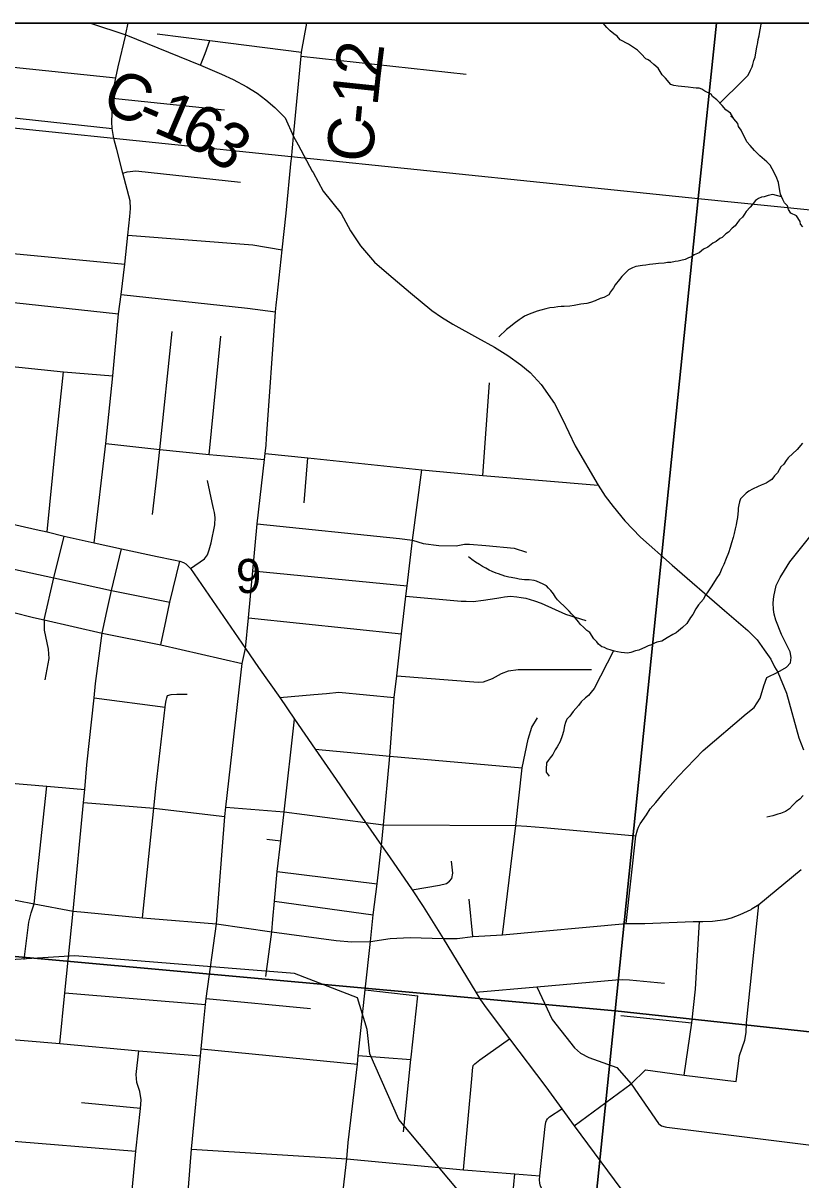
# Model space of a CAD drawing. Extents: x 0 to 34, y -2 to 22.
# Drawn here: x 5.715 to 6.671, y 19.479 to 20.9 of the extents above; entities that cross this region are included whole.
import ezdxf

# ---------------------------------------------------------------- set-up
doc = ezdxf.new("R2010")
doc.units = 0
for name, color, linetype in [('Default', 7, 'Continuous'), ('GM_X_City_Street', 7, 'Continuous'), ('GM_X_County_Road', 7, 'Continuous'), ('GM_X_County_Road_Text', 7, 'Continuous'), ('GM_X_Minor_River', 7, 'Continuous'), ('GM_X_Rail_Line', 7, 'Continuous'), ('GM_X_Section', 7, 'Continuous'), ('GM_X_Section_Text', 7, 'Continuous'), ('GM_X_Township_Road', 7, 'Continuous'), ('SH_Cut_Line', 7, 'Continuous'), ('SH_Data', 7, 'Continuous')]:
    doc.layers.add(name, color=color, linetype=linetype)

msp = doc.modelspace()

# ---------------------------------------------------------------- linework, layer by layer
at = {"layer": 'Default'}
for points in [[(6.5677, 20.9), (5.5559, 20.9), (5.5442, 20.7879), (6.545, 20.6847)], [(7.5861, 20.9), (6.5677, 20.9), (6.545, 20.6847), (7.556, 20.5828)]]:
    msp.add_lwpolyline(points, close=True, dxfattribs=at)
at = {"layer": 'GM_X_City_Street'}
for p, q in [((5.5426, 20.8625), (5.8293, 20.833)), ((5.8442, 20.6398), (5.9979, 20.6276)), ((5.9979, 20.6276), (6.0338, 20.6217)), ((5.6947, 20.618), (5.8404, 20.6041)), ((5.6889, 20.5585), (5.8326, 20.5432)), ((5.8357, 20.5667), (5.991, 20.5499)), ((5.991, 20.5499), (6.0255, 20.5455)), ((5.9441, 20.3701), (5.9584, 20.5157)), ((6.2803, 20.3443), (6.2886, 20.4581)), ((5.9722, 20.3677), (6.0119, 20.3641)), ((6.061, 20.3109), (6.0653, 20.366)), ((5.9978, 20.2273), (6.1873, 20.2088)), ((5.8242, 20.2031), (5.8955, 20.1888)), ((5.9922, 20.1698), (6.1806, 20.15)), ((5.8028, 20.0713), (5.8901, 20.0599)), ((6.0148, 19.898), (6.0321, 19.8958)), ((6.0277, 19.8583), (6.1504, 19.8429)), ((6.0242, 19.8218), (6.1458, 19.8051)), ((6.2681, 19.7782), (6.2636, 19.8243)), ((6.0136, 19.7293), (6.0209, 19.784)), ((5.7665, 19.7093), (5.9396, 19.6946)), ((6.1358, 19.713), (6.2003, 19.7054)), ((5.9404, 19.7023), (6.0684, 19.6897)), ((6.45, 19.6814), (6.5371, 19.6724)), ((5.9343, 19.6403), (6.1263, 19.6215)), ((6.1272, 19.632), (6.192, 19.6272)), ((5.8596, 19.5672), (5.787, 19.5739)), ((5.6223, 19.5336), (5.854, 19.5145)), ((6.3107, 19.3928), (6.3197, 19.4868))]:
    msp.add_line(p, q, dxfattribs=at)
for points in [[(5.5362, 20.8025), (5.5979, 20.7958), (5.6528, 20.7895), (5.7117, 20.783), (5.8247, 20.7706)], [(5.8381, 20.7158), (5.8433, 20.7173), (5.854, 20.7186), (5.9824, 20.7047)], [(5.8745, 20.2965), (5.8797, 20.3424), (5.8835, 20.3764), (5.8985, 20.5213)], [(5.3723, 20.5125), (5.4481, 20.5052), (5.4952, 20.5), (5.5069, 20.4989), (5.5672, 20.4926), (5.5757, 20.4918), (5.6223, 20.4867), (5.6349, 20.4853), (5.6824, 20.4803), (5.7652, 20.4718), (5.8255, 20.4667)], [(5.7448, 20.2751), (5.7552, 20.3787), (5.7652, 20.4718)], [(5.817, 20.3837), (5.8835, 20.3764), (5.9441, 20.3701), (5.9722, 20.3677)], [(6.1558, 19.89), (6.1584, 19.9154), (6.1659, 19.9998), (6.1716, 20.0719), (6.1746, 20.0984), (6.1806, 20.15), (6.1859, 20.1964), (6.1873, 20.2088), (6.1938, 20.2652), (6.2055, 20.3514)], [(5.921, 20.2302), (5.9383, 20.2423), (5.9421, 20.2472), (5.9441, 20.253), (5.9466, 20.2616), (5.9509, 20.2837), (5.9514, 20.2929), (5.9507, 20.2989), (5.9495, 20.304), (5.9478, 20.3112), (5.9419, 20.3382)], [(6.6431, 20.1028), (6.6535, 20.1089), (6.6584, 20.1145), (6.6594, 20.1209), (6.6581, 20.1278), (6.6475, 20.1493), (6.6405, 20.1667), (6.6386, 20.1742), (6.6375, 20.1801), (6.6374, 20.1882), (6.6382, 20.1957), (6.641, 20.2095), (6.6458, 20.2193), (6.6512, 20.2278), (6.6577, 20.2386), (6.7186, 20.3145)], [(6.0029, 20.2853), (6.1781, 20.2672), (6.1938, 20.2652), (6.2069, 20.261), (6.2264, 20.2584), (6.2475, 20.2582), (6.2578, 20.26), (6.2639, 20.2603), (6.2842, 20.2583), (6.3187, 20.2553), (6.3341, 20.2504)], [(5.5365, 20.2691), (5.644, 20.2442), (5.6871, 20.2331), (5.753, 20.2188), (5.8242, 20.2031)], [(5.7414, 20.1671), (5.753, 20.2188), (5.7659, 20.27)], [(5.8184, 20.1773), (5.8242, 20.2031), (5.8361, 20.2544)], [(5.8846, 20.1366), (5.8914, 20.1673), (5.8955, 20.1888), (5.9081, 20.2391)], [(5.5169, 20.2194), (5.6331, 20.1925), (5.6762, 20.183), (5.7281, 20.17)], [(6.1859, 20.1964), (6.2539, 20.1902), (6.2601, 20.1902), (6.2685, 20.1899), (6.281, 20.1912), (6.2974, 20.1939), (6.3025, 20.1946), (6.3072, 20.1956), (6.3145, 20.1962), (6.3221, 20.1954), (6.3276, 20.1947), (6.3331, 20.194), (6.3439, 20.1907), (6.3519, 20.1878), (6.3819, 20.1741), (6.407, 20.1665)], [(5.7604, 19.6469), (5.7665, 19.7093), (5.777, 19.8093), (5.7896, 19.9428), (5.7914, 19.9589), (5.7937, 19.9893), (5.8028, 20.0713), (5.8042, 20.0892), (5.8127, 20.151), (5.8184, 20.1773)], [(5.7281, 20.17), (5.7414, 20.1671), (5.8127, 20.151), (5.8846, 20.1366), (5.9848, 20.1137)], [(5.7414, 20.1671), (5.7414, 20.1544), (5.7463, 20.131), (5.7469, 20.1197), (5.7419, 20.0934)], [(6.1746, 20.0984), (6.2746, 20.0905), (6.2812, 20.091), (6.2922, 20.0953), (6.3035, 20.1011), (6.3118, 20.1045), (6.3237, 20.1061), (6.4138, 20.1064)], [(6.4739, 19.9168), (6.4814, 19.9277), (6.4862, 19.9349), (6.4928, 19.9429), (6.5042, 19.9564), (6.5204, 19.9749), (6.5511, 20.0067), (6.6042, 20.0518), (6.6137, 20.0595), (6.6214, 20.0711), (6.6257, 20.0861), (6.6295, 20.0964), (6.6431, 20.1028)], [(5.8901, 20.0599), (5.8904, 20.0636), (5.891, 20.0681), (5.8919, 20.0716), (5.893, 20.0741), (5.8974, 20.0757), (5.9043, 20.0758), (5.9168, 20.0758)], [(6.031, 20.0717), (6.0727, 20.0754), (6.0883, 20.0769), (6.1034, 20.0782), (6.1716, 20.0719)], [(5.8622, 19.8013), (5.8762, 19.9358), (5.8791, 19.9642), (5.8901, 20.0599)], [(6.0209, 19.784), (6.0221, 19.7995), (6.0242, 19.8218), (6.0277, 19.8583), (6.0321, 19.8958), (6.0363, 19.9314), (6.049, 20.0452)], [(6.3045, 19.7805), (6.3208, 19.9147), (6.3286, 19.9854), (6.3363, 20.0205), (6.3405, 20.0352), (6.3475, 20.0469)], [(6.0743, 20.0083), (6.1659, 19.9998), (6.3286, 19.9854)], [(5.696, 19.967), (5.7445, 19.963), (5.7914, 19.9589)], [(5.7166, 19.7502), (5.7223, 19.7959), (5.7252, 19.8073), (5.7288, 19.8186), (5.7445, 19.963)], [(5.7896, 19.9428), (5.8762, 19.9358), (5.9632, 19.9256)], [(5.9644, 19.9373), (6.0363, 19.9314), (6.1362, 19.9184), (6.1584, 19.9154), (6.3208, 19.9147), (6.3344, 19.9139), (6.3548, 19.9122), (6.4683, 19.9018)], [(6.4567, 19.7942), (6.4683, 19.9018), (6.4704, 19.9092), (6.4716, 19.9127), (6.4739, 19.9168)], [(6.1935, 19.8358), (6.2271, 19.8413), (6.2357, 19.8433), (6.2393, 19.8461), (6.2423, 19.8495), (6.2434, 19.8559), (6.2418, 19.8707)], [(6.5918, 19.6002), (6.596, 19.6322), (6.6022, 19.6511), (6.6039, 19.6605), (6.6045, 19.6724), (6.6194, 19.8178)], [(6.528, 19.6082), (6.5371, 19.6724), (6.5416, 19.7135), (6.5467, 19.7969)], [(6.2719, 19.7099), (6.3467, 19.7164), (6.4438, 19.7251), (6.4522, 19.7256), (6.4606, 19.7249), (6.5037, 19.721)], [(6.1828, 19.5386), (6.192, 19.6272), (6.1923, 19.63), (6.2003, 19.7054)], [(6.3467, 19.7164), (6.3655, 19.6762), (6.3932, 19.6417), (6.4006, 19.635), (6.4107, 19.6299), (6.445, 19.6176), (6.4627, 19.5973)], [(5.4355, 19.674), (5.5708, 19.6629), (5.6385, 19.657), (5.7604, 19.6469), (5.8575, 19.6381), (5.9334, 19.6318)], [(6.2566, 19.4917), (6.2673, 19.6079), (6.2678, 19.614), (6.2685, 19.6197), (6.2706, 19.6221), (6.2766, 19.6269), (6.3131, 19.6527)], [(5.8266, 19.2889), (5.8302, 19.2918), (5.8333, 19.2974), (5.834, 19.3028), (5.8363, 19.3336), (5.8443, 19.4023), (5.8486, 19.4579), (5.854, 19.5145), (5.8596, 19.5672), (5.8604, 19.5777), (5.8587, 19.5879), (5.8552, 19.599), (5.8544, 19.609), (5.8575, 19.6381)], [(6.3927, 19.5459), (6.4627, 19.5973), (6.4802, 19.6144), (6.5248, 19.6086), (6.528, 19.6082), (6.5918, 19.6002)], [(6.4627, 19.5973), (6.4962, 19.5486), (6.4984, 19.547), (6.5001, 19.546), (6.5046, 19.5445), (6.5064, 19.5442), (6.9768, 19.4858)], [(6.4415, 19.3501), (6.3546, 19.4656), (6.3512, 19.4716), (6.3503, 19.4752), (6.3501, 19.4793), (6.3504, 19.4845), (6.3571, 19.5449), (6.3579, 19.5501), (6.3585, 19.5524), (6.3597, 19.5544), (6.3625, 19.557), (6.3774, 19.5668)], [(5.9224, 19.5172), (6.1133, 19.5051), (6.2566, 19.4917), (6.3197, 19.4868), (6.3504, 19.4845)]]:
    msp.add_lwpolyline(points, dxfattribs=at)
at = {"layer": 'GM_X_County_Road'}
for p, q in [((5.7982, 20.9), (5.8415, 20.8855)), ((5.8265, 20.7609), (5.8247, 20.7706)), ((6.0451, 20.7329), (6.0478, 20.7608))]:
    msp.add_line(p, q, dxfattribs=at)
for points in [[(5.8415, 20.8855), (5.8417, 20.8867), (5.8444, 20.9)], [(6.0478, 20.7608), (6.0573, 20.8595), (6.0577, 20.8642), (6.0639, 20.9)], [(5.8293, 20.833), (5.832, 20.8462), (5.8415, 20.8855)], [(5.8415, 20.8855), (5.9071, 20.8592), (5.9333, 20.8482), (5.9592, 20.8374), (5.9734, 20.8306), (5.9903, 20.8218), (6.0029, 20.8138), (6.0136, 20.8058), (6.0246, 20.7962), (6.0376, 20.7839), (6.0478, 20.7608), (6.0533, 20.7507), (6.0708, 20.7184), (6.0718, 20.7166)], [(5.8803, 20.8868), (5.9449, 20.8786), (6.0577, 20.8642)], [(5.9333, 20.8482), (5.9392, 20.8629), (5.9449, 20.8786)], [(5.8252, 20.808), (5.8256, 20.8148), (5.8293, 20.833)], [(5.8247, 20.7706), (5.8246, 20.7787), (5.825, 20.7891), (5.8252, 20.808)], [(5.8029, 20.2617), (5.817, 20.3837), (5.8255, 20.4667), (5.8326, 20.5432), (5.8357, 20.5667), (5.8404, 20.6041), (5.8442, 20.6398), (5.8466, 20.6626), (5.8474, 20.6723), (5.8468, 20.6817), (5.8381, 20.7158), (5.8304, 20.7449), (5.8279, 20.755), (5.8265, 20.7609)], [(6.0275, 20.5642), (6.0338, 20.6217), (6.0387, 20.6667), (6.0449, 20.7311), (6.0451, 20.7329)], [(6.0718, 20.7166), (6.0842, 20.6937), (6.1061, 20.6664), (6.1176, 20.6448), (6.1302, 20.6264), (6.1473, 20.6066), (6.1649, 20.5911), (6.1914, 20.5686), (6.2178, 20.5469), (6.2295, 20.5388), (6.2435, 20.5304), (6.274, 20.5137), (6.2949, 20.5021), (6.3113, 20.492), (6.3272, 20.4802), (6.3385, 20.4709), (6.3519, 20.4561), (6.3686, 20.4329), (6.3784, 20.4137), (6.3939, 20.381), (6.422, 20.3325), (6.4306, 20.3191), (6.4407, 20.3065), (6.4549, 20.2886), (6.4742, 20.2686), (6.5129, 20.2344), (6.5774, 20.1785), (6.606, 20.1542), (6.6175, 20.1425), (6.626, 20.1304), (6.6343, 20.1187), (6.6389, 20.1095), (6.6431, 20.1028), (6.6535, 20.077), (6.6688, 20.0221), (6.6745, 20.0075)], [(6.0139, 20.3818), (6.0146, 20.3901), (6.0255, 20.5455), (6.0264, 20.5536), (6.0275, 20.5642)], [(5.9885, 20.1319), (5.9922, 20.1698), (5.9978, 20.2273), (6.0029, 20.2853), (6.0119, 20.3641), (6.013, 20.3714), (6.0139, 20.3818)], [(6.013, 20.3714), (6.0653, 20.366), (6.2055, 20.3514), (6.2803, 20.3443), (6.422, 20.3325)], [(5.6923, 20.2871), (5.7313, 20.2782), (5.7448, 20.2751), (5.7659, 20.27), (5.8029, 20.2617), (5.8361, 20.2544), (5.8802, 20.2451), (5.9002, 20.2408), (5.9081, 20.2391)], [(5.9081, 20.2391), (5.9123, 20.2377), (5.9154, 20.2361), (5.9179, 20.2335), (5.921, 20.2302)], [(5.921, 20.2302), (5.9885, 20.1319), (6.0047, 20.1087), (6.031, 20.0717), (6.049, 20.0452), (6.0743, 20.0083), (6.1, 19.9711), (6.1362, 19.9184), (6.1558, 19.89), (6.1657, 19.876), (6.1935, 19.8358), (6.2069, 19.815), (6.2317, 19.776), (6.2719, 19.7099), (6.2775, 19.7006), (6.2844, 19.6909), (6.3131, 19.6527), (6.3577, 19.5936), (6.3774, 19.5668), (6.3927, 19.5459), (6.4991, 19.4022)], [(5.9014, 19.2974), (5.9131, 19.3966), (5.9224, 19.5172), (5.9334, 19.6318), (5.9343, 19.6403), (5.9375, 19.6743), (5.9396, 19.6946), (5.9404, 19.7023), (5.9529, 19.7939), (5.9632, 19.9256), (5.9644, 19.9373), (5.9848, 20.1137), (5.9885, 20.1319)], [(6.08, 19.2123), (6.099, 19.3814), (6.1133, 19.5051), (6.115, 19.5254), (6.1263, 19.6215), (6.1272, 19.632), (6.1358, 19.713), (6.1423, 19.7722), (6.1458, 19.8051), (6.1504, 19.8429), (6.1558, 19.89)], [(6.6116, 19.8127), (6.6194, 19.8178), (6.6716, 19.8607)], [(5.4525, 19.8485), (5.6558, 19.829), (5.6871, 19.8259), (5.6955, 19.8249), (5.7082, 19.8225), (5.7288, 19.8186), (5.777, 19.8093), (5.791, 19.808), (5.8622, 19.8013), (5.8723, 19.8005)], [(6.2317, 19.776), (6.249, 19.776), (6.2681, 19.7782), (6.3045, 19.7805), (6.4567, 19.7942), (6.4793, 19.7942), (6.539, 19.7968), (6.5467, 19.7969), (6.5507, 19.7969), (6.5627, 19.7971), (6.5781, 19.7993), (6.5858, 19.8014), (6.5968, 19.8052), (6.6101, 19.8116), (6.6116, 19.8127)], [(5.8723, 19.8005), (5.9529, 19.7939), (6.0209, 19.784), (6.1002, 19.7735), (6.1192, 19.7716), (6.1423, 19.7722), (6.1665, 19.7758), (6.1911, 19.7772), (6.2317, 19.776)]]:
    msp.add_lwpolyline(points, dxfattribs=at)
at = {"layer": 'GM_X_Minor_River'}
for points in [[(6.6735, 20.6497), (6.671, 20.6532), (6.6703, 20.6563), (6.6659, 20.6632), (6.6588, 20.6665), (6.6559, 20.6711), (6.6549, 20.6757), (6.6511, 20.6793), (6.649, 20.6835), (6.6461, 20.6901), (6.6455, 20.6939), (6.6438, 20.7042), (6.641, 20.7115), (6.6359, 20.7212), (6.6334, 20.7255), (6.6293, 20.7298), (6.6208, 20.7369), (6.6141, 20.7435), (6.6089, 20.7498), (6.6049, 20.7544), (6.6031, 20.7579), (6.6002, 20.7633), (6.5977, 20.7684), (6.5947, 20.773), (6.5937, 20.7768), (6.5889, 20.7823), (6.5849, 20.7893), (6.5789, 20.7936), (6.5745, 20.7987), (6.5679, 20.8057), (6.5627, 20.8097), (6.5612, 20.8128), (6.5533, 20.8164), (6.5496, 20.8188), (6.5462, 20.8201), (6.5424, 20.8202), (6.539, 20.8206), (6.5329, 20.8212), (6.5204, 20.8227), (6.5151, 20.8236), (6.5113, 20.8248), (6.5047, 20.8323), (6.5006, 20.8366), (6.4959, 20.8447), (6.4907, 20.849), (6.4866, 20.853), (6.4836, 20.8549), (6.4806, 20.8562), (6.4751, 20.8624), (6.4703, 20.8667), (6.4594, 20.8743), (6.4493, 20.8795), (6.4456, 20.8838), (6.4415, 20.887), (6.4367, 20.8905), (6.4326, 20.8948), (6.4281, 20.9)], [(6.5718, 20.8016), (6.5997, 20.8292), (6.6024, 20.8322), (6.6063, 20.8359), (6.6092, 20.8423), (6.6116, 20.8464), (6.6124, 20.8494), (6.6133, 20.854), (6.6149, 20.8581), (6.6154, 20.8612), (6.6172, 20.8706), (6.6185, 20.8763), (6.6189, 20.8797), (6.6198, 20.8843), (6.6207, 20.8896), (6.6216, 20.8937), (6.6225, 20.8987), (6.6228, 20.9)], [(6.5882, 20.7835), (6.585, 20.7852)], [(6.6475, 20.6868), (6.6366, 20.6896), (6.6309, 20.6882), (6.6263, 20.6868), (6.6228, 20.6862), (6.619, 20.6847), (6.6155, 20.6822), (6.6112, 20.677), (6.6088, 20.674), (6.6041, 20.6688), (6.6021, 20.6654), (6.5997, 20.6617), (6.5958, 20.6583), (6.5934, 20.655), (6.5907, 20.6509), (6.5868, 20.6483), (6.5825, 20.6431), (6.579, 20.6413), (6.5747, 20.6369), (6.5716, 20.6354), (6.5673, 20.6317), (6.5631, 20.6299), (6.5569, 20.6248), (6.5515, 20.6226), (6.5464, 20.6178), (6.5403, 20.6153), (6.5368, 20.6128), (6.533, 20.6117), (6.5291, 20.6096), (6.5237, 20.6086), (6.5203, 20.6075), (6.5169, 20.6072), (6.5115, 20.6062), (6.5073, 20.606), (6.5031, 20.6053), (6.4963, 20.6048), (6.4932, 20.6045), (6.4894, 20.6038), (6.4852, 20.6036), (6.4806, 20.6029), (6.4768, 20.6023), (6.4684, 20.601), (6.4642, 20.5996), (6.4595, 20.597), (6.456, 20.5937), (6.4513, 20.5889), (6.4482, 20.5852), (6.4431, 20.5785), (6.4411, 20.5751), (6.4371, 20.5699), (6.4351, 20.5665), (6.429, 20.5632), (6.4247, 20.5618), (6.4186, 20.559), (6.4128, 20.5568), (6.4082, 20.5558), (6.401, 20.5549), (6.3926, 20.5532), (6.3872, 20.5526), (6.3804, 20.552), (6.3766, 20.5518), (6.3724, 20.5515), (6.3682, 20.5508), (6.3628, 20.5502), (6.3579, 20.5492), (6.3517, 20.5475), (6.3471, 20.5461), (6.3375, 20.5426), (6.3317, 20.5401), (6.3287, 20.5382), (6.3252, 20.5357), (6.319, 20.5313), (6.3143, 20.5276), (6.3096, 20.5239), (6.2999, 20.5147)], [(6.6732, 20.3843), (6.6665, 20.3765), (6.6556, 20.3661), (6.6532, 20.3627), (6.6504, 20.3582), (6.6465, 20.3549), (6.6426, 20.3478), (6.639, 20.3441), (6.6355, 20.3396), (6.6324, 20.3374), (6.6285, 20.3349), (6.6224, 20.3327), (6.6189, 20.3309), (6.612, 20.3277), (6.6073, 20.3252), (6.6042, 20.3226), (6.6007, 20.3196), (6.5972, 20.3156), (6.596, 20.3122), (6.5951, 20.3084), (6.5942, 20.3042), (6.5941, 20.3012), (6.5936, 20.2974), (6.5935, 20.2928), (6.5922, 20.2867), (6.5918, 20.2837), (6.5905, 20.2788), (6.5892, 20.2731), (6.5879, 20.2682), (6.5862, 20.2618), (6.5845, 20.2561), (6.5825, 20.2493), (6.5796, 20.2425), (6.5767, 20.235), (6.5743, 20.2301), (6.5715, 20.2241), (6.5671, 20.2174), (6.562, 20.2091), (6.556, 20.2002), (6.5537, 20.1972), (6.5516, 20.1927), (6.5454, 20.1856), (6.5422, 20.1807), (6.5386, 20.1736), (6.5358, 20.1699), (6.5311, 20.1628), (6.5256, 20.1576), (6.5209, 20.1535), (6.5178, 20.1513), (6.514, 20.1492), (6.507, 20.1452), (6.5004, 20.1412), (6.4943, 20.1398), (6.4912, 20.1384), (6.4878, 20.1366), (6.4835, 20.1352), (6.4805, 20.1337), (6.472, 20.1301), (6.4682, 20.1291), (6.4624, 20.127), (6.4582, 20.1263), (6.4544, 20.1265), (6.4506, 20.1269), (6.4457, 20.1278), (6.4423, 20.1287), (6.4381, 20.13), (6.4329, 20.1316), (6.4299, 20.1332), (6.4265, 20.1341), (6.4224, 20.1372), (6.4205, 20.1403), (6.4168, 20.1439)], [(6.4168, 20.1439), (6.4117, 20.1516), (6.4084, 20.154), (6.4039, 20.158), (6.4006, 20.1615), (6.398, 20.1646), (6.3921, 20.1716), (6.3892, 20.1747), (6.3866, 20.1779), (6.3832, 20.181), (6.3803, 20.1841), (6.3755, 20.1885), (6.3721, 20.1916), (6.3696, 20.1951), (6.3674, 20.199), (6.3641, 20.2032), (6.3611, 20.206), (6.3585, 20.2091), (6.3544, 20.2111), (6.3465, 20.2148), (6.3435, 20.2156), (6.3374, 20.2162), (6.3317, 20.2163), (6.3249, 20.2173), (6.3219, 20.2178), (6.3154, 20.2191), (6.3124, 20.2195), (6.3075, 20.2208), (6.2996, 20.2237), (6.2966, 20.2246), (6.2917, 20.2266), (6.2883, 20.2282), (6.2842, 20.2306), (6.2801, 20.2326), (6.2763, 20.235), (6.2715, 20.2382), (6.267, 20.2414), (6.2629, 20.2445)], [(6.4408, 20.1291), (6.4171, 20.0829), (6.4135, 20.0785), (6.4104, 20.0744), (6.4065, 20.0714), (6.4011, 20.0666), (6.3979, 20.0618), (6.3912, 20.0547), (6.3873, 20.0491), (6.3837, 20.0454), (6.3821, 20.0413), (6.3809, 20.0371), (6.3795, 20.0299), (6.3779, 20.0246), (6.3754, 20.0178), (6.3718, 20.0111), (6.3694, 20.0077), (6.3666, 20.0017), (6.3631, 19.9976), (6.3607, 19.9946), (6.3587, 19.9916), (6.3581, 19.9837), (6.3584, 19.9802), (6.3621, 19.9752)], [(6.674, 19.9516), (6.6701, 19.9468), (6.6654, 19.9435), (6.6611, 19.939), (6.6572, 19.9353), (6.6522, 19.932), (6.6464, 19.9295), (6.643, 19.9285), (6.6368, 19.9264), (6.6296, 19.925)]]:
    msp.add_lwpolyline(points, dxfattribs=at)
at = {"layer": 'GM_X_Rail_Line'}
for points in [[(7.2924, 18.0527), (7.3254, 18.3889), (7.3765, 18.917), (7.3781, 18.9333), (7.4316, 19.4382), (7.4466, 19.581), (7.5261, 20.3339), (7.5512, 20.5718), (7.5526, 20.5853), (7.5548, 20.6102), (7.5809, 20.9), (2.1, 20.9)], [(6.6766, 18.8917), (6.6605, 18.9564), (6.6008, 19.034), (6.5411, 19.0908), (6.4665, 19.1654), (6.4307, 19.2311), (6.4367, 19.261), (6.4069, 19.3147), (6.2875, 19.4222), (6.1771, 19.5536), (6.1413, 19.6343), (6.1384, 19.6641), (6.1264, 19.703), (6.0488, 19.7328), (5.7789, 19.7547), (5.6798, 19.7484), (5.5911, 19.7272), (5.5025, 19.7251), (5.4223, 19.7251), (5.224, 19.7547)]]:
    msp.add_lwpolyline(points, dxfattribs=at)
at = {"layer": 'GM_X_Section'}
for points in [[(6.545, 20.6847), (6.443, 19.687), (5.4431, 19.7776), (5.4475, 19.8207), (5.5442, 20.7879)], [(6.545, 20.6847), (7.556, 20.5828), (7.4489, 19.5784), (6.443, 19.687)], [(5.4431, 19.7776), (6.443, 19.687), (6.3407, 18.6907), (5.3451, 18.7715)], [(7.4489, 19.5784), (7.3433, 18.5849), (6.3407, 18.6907), (6.443, 19.687)]]:
    msp.add_lwpolyline(points, close=True, dxfattribs=at)
at = {"layer": 'GM_X_Township_Road'}
for p, q in [((6.0573, 20.8595), (6.2598, 20.8375)), ((5.8252, 20.808), (5.9627, 20.7936))]:
    msp.add_line(p, q, dxfattribs=at)
at = {"layer": 'SH_Cut_Line'}
msp.add_lwpolyline([(6.0485, 14.702), (6.1464, 14.7771), (6.2416, 14.8366), (6.3391, 14.8719), (6.8207, 14.994), (7.0052, 15.0295), (7.018, 15.0319), (7.3068, 15.0956), (7.4995, 15.1593), (7.5948, 15.214), (7.6912, 15.289), (7.9856, 15.5639), (8.2003, 15.8586), (8.2596, 15.9572), (8.5337, 16.2495), (8.6286, 16.3042), (8.7283, 16.3459), (8.827, 16.358), (8.9, 16.3574), (8.9, 20.9), (2.1, 20.9)], dxfattribs=at)
at = {"layer": 'SH_Data'}
msp.add_line((2.1, 20.9), (8.9, 20.9), dxfattribs=at)

# ---------------------------------------------------------------- texts
at = {"layer": 'GM_X_County_Road_Text'}
for s, rotation, p in [('2', 82.813, (6.1544, 20.8317)), ('C', 336.9534, (5.8091, 20.7942)), ('1', 83.9872, (6.1508, 20.7972)), ('1', 336.8978, (5.8735, 20.7668)), ('-', 336.9411, (5.852, 20.7759)), ('6', 334.8629, (5.9052, 20.7533)), ('-', 84.5648, (6.1486, 20.7741)), ('C', 84.7498, (6.1443, 20.7277)), ('3', 324.229, (5.9344, 20.7398))]:
    msp.add_text(s, height=0.0568, rotation=rotation, dxfattribs=at).set_placement(p)
at = {"layer": 'GM_X_Section_Text'}
msp.add_text('9', height=0.0419, rotation=0, dxfattribs=at).set_placement((5.9769, 20.2001))

doc.saveas('drawing.dxf')
